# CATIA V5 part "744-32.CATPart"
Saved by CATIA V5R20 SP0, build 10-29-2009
Part number: 744-32
Revision: TUTTO
Definition: NON CONOSCIUTO
Nomenclature: 744-32
Source: Unknown
Bounding box of the stored display mesh (mm): x -28 to 28, y -28.5 to 28, z -30 to 45
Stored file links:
  C:\Users\Utente\Desktop\IO LAVORO\3D X SITO CF\X SITO\744\744-32.CATPart
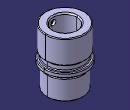
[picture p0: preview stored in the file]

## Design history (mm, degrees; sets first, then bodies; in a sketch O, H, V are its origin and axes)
Body1 "744-32 sol1" (main body)
  Solid1: solid without history
Body2 "IDV1M8_Ingrassatore-1"
  Solid2: solid without history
